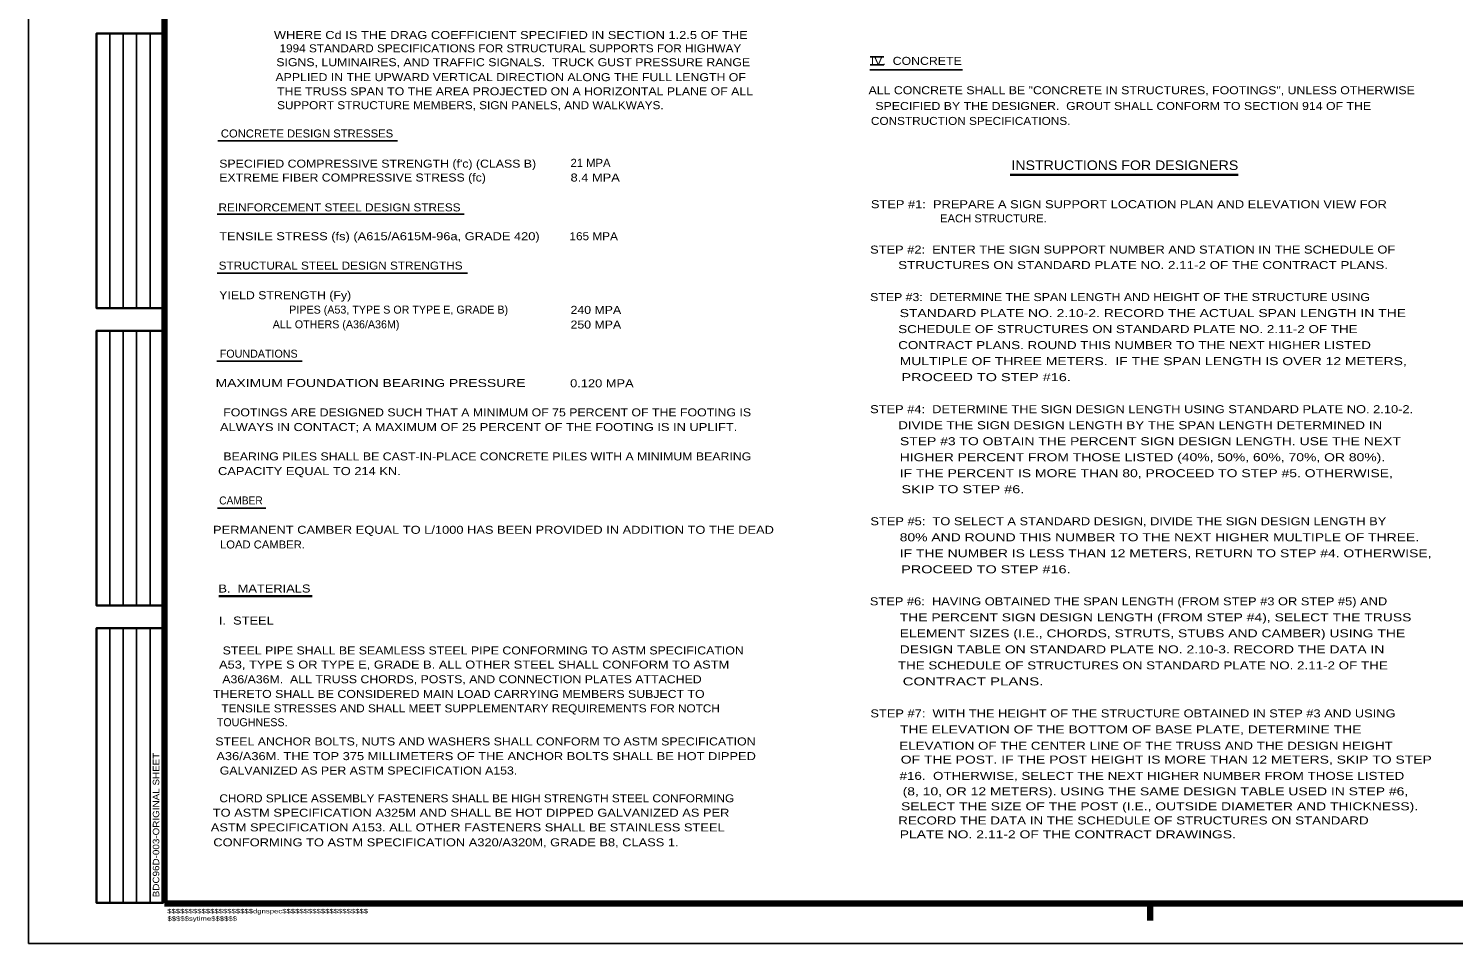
# Model space of a CAD drawing. Extents: x 312601.858 to 312602.699, y 144420.109 to 144420.704.
# Drawn here: x 312601.858 to 312602.392, y 144420.109 to 144420.452 of the extents above; entities that cross this region are included whole.
import ezdxf
from ezdxf.enums import TextEntityAlignment as Align

# ---------------------------------------------------------------- set-up
doc = ezdxf.new("R2010")
doc.units = 0
doc.header["$LTSCALE"] = 0.0012
for name, color, linetype, lineweight in [('1', 7, 'Continuous', 25), ('2', 7, 'Continuous', 25), ('39', 7, 'Continuous', 25), ('60', 7, 'Continuous', 25)]:
    doc.layers.add(name, color=color, linetype=linetype, lineweight=lineweight)

msp = doc.modelspace()

# ---------------------------------------------------------------- linework, layer by layer
at = {"layer": '1'}
for p, q in [((312602.1733, 144420.4417), (312602.1784, 144420.4417)), ((312602.1773, 144420.4417), (312602.178, 144420.4417)), ((312602.1732, 144420.4369), (312602.2079, 144420.4369)), ((312602.1733, 144420.4387), (312602.1784, 144420.4387)), ((312601.9288, 144420.4102), (312601.9961, 144420.4102)), ((312601.9285, 144420.3828), (312602.0211, 144420.3828)), ((312601.9285, 144420.3607), (312602.0224, 144420.3607)), ((312601.9284, 144420.3277), (312601.9604, 144420.3277)), ((312601.9286, 144420.2726), (312601.9468, 144420.2726))]:
    msp.add_line(p, q, dxfattribs=at)
at = {"layer": '1', "lineweight": 35}
for p, q in [((312602.2258, 144420.3975), (312602.3113, 144420.3975)), ((312601.9291, 144420.2396), (312601.9641, 144420.2396))]:
    msp.add_line(p, q, dxfattribs=at)
at = {"layer": '39'}
for q in [(312601.8578, 144420.7035), (312602.6988, 144420.1095), (312602.6988, 144420.1095)]:
    msp.add_line((312601.8578, 144420.1095), q, dxfattribs=at)
at = {"layer": '39', "lineweight": 158}
for p, q in [((312601.9088, 144420.1247), (312601.9088, 144420.6645)), ((312601.9088, 144420.1245), (312602.6838, 144420.1245)), ((312601.9088, 144420.1245), (312602.6838, 144420.1245)), ((312602.2783, 144420.1181), (312602.2783, 144420.1245))]:
    msp.add_line(p, q, dxfattribs=at)
at = {"layer": '39'}
msp.add_lwpolyline([(312601.8578, 144420.1095), (312602.6988, 144420.1095), (312602.6988, 144420.7035)], dxfattribs=at)
at = {"layer": '39', "lineweight": 158}
msp.add_lwpolyline([(312601.9088, 144420.1245), (312602.6838, 144420.1245), (312602.6838, 144420.6645)], dxfattribs=at)
at = {"layer": '60'}
for p, q in [((312601.8883, 144420.3475), (312601.8883, 144420.4505)), ((312601.8933, 144420.3475), (312601.8933, 144420.4505)), ((312601.8983, 144420.3475), (312601.8983, 144420.4505)), ((312601.9034, 144420.3475), (312601.9034, 144420.4505)), ((312601.8883, 144420.2361), (312601.8883, 144420.3391)), ((312601.8933, 144420.2361), (312601.8933, 144420.3391)), ((312601.8983, 144420.2361), (312601.8983, 144420.3391)), ((312601.9034, 144420.2361), (312601.9034, 144420.3391)), ((312601.8883, 144420.1247), (312601.8883, 144420.2277)), ((312601.8933, 144420.1247), (312601.8933, 144420.2277)), ((312601.8983, 144420.1247), (312601.8983, 144420.2277)), ((312601.9034, 144420.1247), (312601.9034, 144420.2277))]:
    msp.add_line(p, q, dxfattribs=at)
at = {"layer": '60', "lineweight": 35}
for points in [[(312601.9084, 144420.3475), (312601.8833, 144420.3475), (312601.8833, 144420.4505), (312601.9084, 144420.4505)], [(312601.9084, 144420.2361), (312601.8833, 144420.2361), (312601.8833, 144420.3391), (312601.9084, 144420.3391)], [(312601.9084, 144420.1247), (312601.8833, 144420.1247), (312601.8833, 144420.2277), (312601.9084, 144420.2277)]]:
    msp.add_lwpolyline(points, dxfattribs=at)

# ---------------------------------------------------------------- texts
at = {"layer": '1'}
for s, width, p in [("SPECIFIED COMPRESSIVE STRENGTH (f'c) (CLASS B)", 1.15, (312601.9293, 144420.4002)), ('21 MPA', 1.05, (312602.061, 144420.4005)), ('EXTREME FIBER COMPRESSIVE STRESS (fc)', 1.15, (312601.9293, 144420.395)), ('8.4 MPA', 1.2, (312602.061, 144420.395)), ('STEP #1:  PREPARE A SIGN SUPPORT LOCATION PLAN AND ELEVATION VIEW FOR', 1.2, (312602.1736, 144420.385)), ('EACH STRUCTURE.', 1.05, (312602.1995, 144420.3797)), ('TENSILE STRESS (fs) (A615/A615M-96a, GRADE 420)', 1.2, (312601.9293, 144420.373)), ('165 MPA', 1.1, (312602.0606, 144420.373)), ('STEP #2:  ENTER THE SIGN SUPPORT NUMBER AND STATION IN THE SCHEDULE OF', 1.2, (312602.1733, 144420.368)), ('          STRUCTURES ON STANDARD PLATE NO. 2.11-2 OF THE CONTRACT PLANS.', 1.25, (312602.1699, 144420.3622)), ('YIELD STRENGTH (Fy)', 1.15, (312601.9293, 144420.3509)), ('STEP #3:  DETERMINE THE SPAN LENGTH AND HEIGHT OF THE STRUCTURE USING', 1.15, (312602.1733, 144420.3502)), ('240 MPA', 1.15, (312602.061, 144420.3454)), ('          STANDARD PLATE NO. 2.10-2. RECORD THE ACTUAL SPAN LENGTH IN THE', 1.3, (312602.1699, 144420.3442)), ('250 MPA', 1.15, (312602.061, 144420.3399)), ('          SCHEDULE OF STRUCTURES ON STANDARD PLATE NO. 2.11-2 OF THE', 1.25, (312602.1699, 144420.3382)), ('          CONTRACT PLANS. ROUND THIS NUMBER TO THE NEXT HIGHER LISTED', 1.25, (312602.1699, 144420.3322)), ('          MULTIPLE OF THREE METERS.  IF THE SPAN LENGTH IS OVER 12 METERS,', 1.3, (312602.1699, 144420.3262)), ('          PROCEED TO STEP #16.', 1.35, (312602.17, 144420.3202)), ('STEP #4:  DETERMINE THE SIGN DESIGN LENGTH USING STANDARD PLATE NO. 2.10-2. ', 1.2, (312602.1733, 144420.3082)), ('          DIVIDE THE SIGN DESIGN LENGTH BY THE SPAN LENGTH DETERMINED IN', 1.25, (312602.1699, 144420.3022)), ('          STEP #3 TO OBTAIN THE PERCENT SIGN DESIGN LENGTH. USE THE NEXT', 1.3, (312602.17, 144420.2962)), ('          HIGHER PERCENT FROM THOSE LISTED (40%, 50%, 60%, 70%, OR 80%). ', 1.3, (312602.1699, 144420.2902)), ('          IF THE PERCENT IS MORE THAN 80, PROCEED TO STEP #5. OTHERWISE,', 1.3, (312602.1699, 144420.2842)), ('          SKIP TO STEP #6.', 1.35, (312602.17, 144420.2782)), ('STEP #5:  TO SELECT A STANDARD DESIGN, DIVIDE THE SIGN DESIGN LENGTH BY', 1.2, (312602.1734, 144420.2662)), ('          80% AND ROUND THIS NUMBER TO THE NEXT HIGHER MULTIPLE OF THREE. ', 1.3, (312602.1699, 144420.2602)), ('          IF THE NUMBER IS LESS THAN 12 METERS, RETURN TO STEP #4. OTHERWISE,', 1.3, (312602.1699, 144420.2542)), ('          PROCEED TO STEP #16.', 1.35, (312602.1699, 144420.2482)), ('STEP #6:  HAVING OBTAINED THE SPAN LENGTH (FROM STEP #3 OR STEP #5) AND', 1.2, (312602.1732, 144420.2362)), ('          THE PERCENT SIGN DESIGN LENGTH (FROM STEP #4), SELECT THE TRUSS ', 1.3, (312602.1699, 144420.2302)), ('          ELEMENT SIZES (I.E., CHORDS, STRUTS, STUBS AND CAMBER) USING THE', 1.3, (312602.1699, 144420.2242)), ('          DESIGN TABLE ON STANDARD PLATE NO. 2.10-3. RECORD THE DATA IN', 1.3, (312602.1699, 144420.2182)), ('          THE SCHEDULE OF STRUCTURES ON STANDARD PLATE NO. 2.11-2 OF THE', 1.25, (312602.1698, 144420.2122)), ('          CONTRACT PLANS.', 1.4, (312602.1699, 144420.2062)), ('STEP #7:  WITH THE HEIGHT OF THE STRUCTURE OBTAINED IN STEP #3 AND USING', 1.2, (312602.1734, 144420.1942)), ('          THE ELEVATION OF THE BOTTOM OF BASE PLATE, DETERMINE THE', 1.3, (312602.17, 144420.1882)), ('          ELEVATION OF THE CENTER LINE OF THE TRUSS AND THE DESIGN HEIGHT', 1.25, (312602.1703, 144420.1821)), ('          OF THE POST. IF THE POST HEIGHT IS MORE THAN 12 METERS, SKIP TO STEP', 1.3, (312602.1703, 144420.1769)), ('          #16.  OTHERWISE, SELECT THE NEXT HIGHER NUMBER FROM THOSE LISTED', 1.25, (312602.1704, 144420.1708)), ('          (8, 10, OR 12 METERS). USING THE SAME DESIGN TABLE USED IN STEP #6,', 1.3, (312602.171, 144420.165)), ('          SELECT THE SIZE OF THE POST (I.E., OUTSIDE DIAMETER AND THICKNESS). ', 1.3, (312602.1704, 144420.1594)), ('          RECORD THE DATA IN THE SCHEDULE OF STRUCTURES ON STANDARD', 1.25, (312602.1699, 144420.1541)), ('          PLATE NO. 2.11-2 OF THE CONTRACT DRAWINGS.', 1.3, (312602.1699, 144420.1489))]:
    msp.add_text(s, height=0.003, dxfattribs=dict(at, width=width)).set_placement(p)
for s, height, width, p in [('INSTRUCTIONS FOR DESIGNERS', 0.0036, 1.1, (312602.2688, 144420.3993)), ('0.120 MPA', 0.003, 1.2, (312602.07275, 144420.3179))]:
    msp.add_text(s, height=height, dxfattribs=dict(at, width=width)).set_placement(p, align=Align.CENTER)
at = {"layer": '2'}
for s, width, p in [('WHERE Cd IS THE DRAG COEFFICIENT SPECIFIED IN SECTION 1.2.5 OF THE', 1.2, (312602.0386, 144420.4484)), ('1994 STANDARD SPECIFICATIONS FOR STRUCTURAL SUPPORTS FOR HIGHWAY', 1.1, (312602.03845, 144420.4434)), ('SIGNS, LUMINAIRES, AND TRAFFIC SIGNALS.  TRUCK GUST PRESSURE RANGE', 1.15, (312602.0395, 144420.4382)), ('IV.  CONCRETE', 1.15, (312602.1906, 144420.4387)), ('APPLIED IN THE UPWARD VERTICAL DIRECTION ALONG THE FULL LENGTH OF', 1.15, (312602.03855, 144420.4326)), ('THE TRUSS SPAN TO THE AREA PROJECTED ON A HORIZONTAL PLANE OF ALL', 1.15, (312602.0402, 144420.4273)), ('ALL CONCRETE SHALL BE "CONCRETE IN STRUCTURES, FOOTINGS", UNLESS OTHERWISE', 1.15, (312602.2751, 144420.4277)), ('SUPPORT STRUCTURE MEMBERS, SIGN PANELS, AND WALKWAYS.', 1.1, (312602.02345, 144420.4221)), ('SPECIFIED BY THE DESIGNER.  GROUT SHALL CONFORM TO SECTION 914 OF THE', 1.15, (312602.2682, 144420.4218)), ('CONSTRUCTION SPECIFICATIONS.', 1.1, (312602.211, 144420.4162)), ('CONCRETE DESIGN STRESSES', 1.05, (312601.9622, 144420.4115)), ('REINFORCEMENT STEEL DESIGN STRESS', 1.1, (312601.9744, 144420.3838)), ('STRUCTURAL STEEL DESIGN STRENGTHS', 1.1, (312601.9748, 144420.362)), ('MAXIMUM FOUNDATION BEARING PRESSURE             ', 1.3, (312601.99545, 144420.318)), ('FOOTINGS ARE DESIGNED SUCH THAT A MINIMUM OF 75 PERCENT OF THE FOOTING IS', 1.15, (312602.02975, 144420.307)), ('ALWAYS IN CONTACT; A MAXIMUM OF 25 PERCENT OF THE FOOTING IS IN UPLIFT.', 1.2, (312602.02655, 144420.3015)), ('BEARING PILES SHALL BE CAST-IN-PLACE CONCRETE PILES WITH A MINIMUM BEARING', 1.15, (312602.0298, 144420.2905)), ('CAPACITY EQUAL TO 214 KN.', 1.2, (312601.9631, 144420.285)), ('CAMBER', 0.95, (312601.93745, 144420.274)), ('PERMANENT CAMBER EQUAL TO L/1000 HAS BEEN PROVIDED IN ADDITION TO THE DEAD', 1.2, (312602.0321, 144420.263)), ('LOAD CAMBER.', 1.05, (312601.9455, 144420.2575)), ('B.  MATERIALS', 1.2, (312601.94625, 144420.241)), ('I.  STEEL', 1.2, (312601.93945, 144420.229)), ('STEEL PIPE SHALL BE SEAMLESS STEEL PIPE CONFORMING TO ASTM SPECIFICATION ', 1.15, (312602.0289, 144420.2178)), ('A53, TYPE S OR TYPE E, GRADE B. ALL OTHER STEEL SHALL CONFORM TO ASTM', 1.2, (312602.02485, 144420.2125)), ('A36/A36M.  ALL TRUSS CHORDS, POSTS, AND CONNECTION PLATES ATTACHED', 1.15, (312602.0203, 144420.207)), ('THERETO SHALL BE CONSIDERED MAIN LOAD CARRYING MEMBERS SUBJECT TO', 1.15, (312602.0191, 144420.2015)), ('TENSILE STRESSES AND SHALL MEET SUPPLEMENTARY REQUIREMENTS FOR NOTCH', 1.1, (312602.02355, 144420.1961)), ('STEEL ANCHOR BOLTS, NUTS AND WASHERS SHALL CONFORM TO ASTM SPECIFICATION', 1.15, (312602.0291, 144420.1837)), ('A36/A36M. THE TOP 375 MILLIMETERS OF THE ANCHOR BOLTS SHALL BE HOT DIPPED', 1.2, (312602.02935, 144420.1782)), ('GALVANIZED AS PER ASTM SPECIFICATION A153.', 1.15, (312601.98525, 144420.1728)), ('CHORD SPLICE ASSEMBLY FASTENERS SHALL BE HIGH STRENGTH STEEL CONFORMING', 1.1, (312602.02585, 144420.1624)), ('TO ASTM SPECIFICATION A325M AND SHALL BE HOT DIPPED GALVANIZED AS PER', 1.2, (312602.0237, 144420.157)), ('ASTM SPECIFICATION A153. ALL OTHER FASTENERS SHALL BE STAINLESS STEEL', 1.2, (312602.02245, 144420.1515)), ('CONFORMING TO ASTM SPECIFICATION A320/A320M, GRADE B8, CLASS 1.', 1.2, (312602.0143, 144420.1459))]:
    msp.add_text(s, height=0.003, dxfattribs=dict(at, width=width)).set_placement(p, align=Align.CENTER)
for s, p in [('     PIPES (A53, TYPE S OR TYPE E, GRADE B)                                     ', (312602.0144, 144420.3455)), ('     ALL OTHERS (A36/A36M)                               ', (312601.9876, 144420.34)), ('FOUNDATIONS', (312601.9441, 144420.329)), ('TOUGHNESS.', (312601.94165, 144420.1909))]:
    msp.add_text(s, height=0.003, dxfattribs=at).set_placement(p, align=Align.CENTER)
at = {"layer": '2', "width": 1.15}
msp.add_text('BDC96D-003-ORIGINAL SHEET', height=0.0024, rotation=90, dxfattribs=at).set_placement((312601.9068, 144420.1539), align=Align.CENTER)
at = {"layer": '2', "width": 1.3}
for s, p in [('$$$$$$$$$$$$$$$$$$$$dgnspec$$$$$$$$$$$$$$$$$$$$', (312601.9098, 144420.1208)), ('$$$$$sytime$$$$$$', (312601.9099, 144420.118))]:
    msp.add_text(s, height=0.001664, dxfattribs=at).set_placement(p)

doc.saveas('drawing.dxf')
